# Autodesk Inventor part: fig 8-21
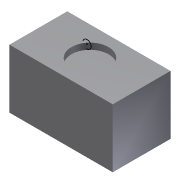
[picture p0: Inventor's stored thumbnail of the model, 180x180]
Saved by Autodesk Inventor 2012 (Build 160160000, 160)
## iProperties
Created: 2011-07
Part Number: fig 8-21
Material: Default
Document SubType Name: Modeling
Designer: CadCim
Density: 1 g/cm^3
Author: CadCim
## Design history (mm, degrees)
sketch "Sketch1"
  geometry: L1 (-18, 10)-(7, 10); L2 (7, 10)-(7, -4); L3 (7, -4)-(-18, -4); L4 (-18, -4)-(-18, 10); 1 further point
  constraints: 8 end point, 2 parallel, 1 horizontal, 1 perpendicular
extrude "Extrusion1" new body sketch "Sketch1" distance "d0" = 14.25; taper "d1" = 0 deg
sketch "Sketch2"
  geometry: C1 r 4.5 at (-5.5, 3); 1 further point
  constraints: 1 centre point
extrude "Extrusion2" cut sketch "Sketch2" distance "d2" = 1.5; taper "d3" = 0 deg
workplane "Work Plane2"
sketch "Sketch4"
  geometry: C1 r 1 at (9, -14); 1 further point
  constraints: 1 centre point
body "Solid1"
other parameters: "d4" = -4.25
